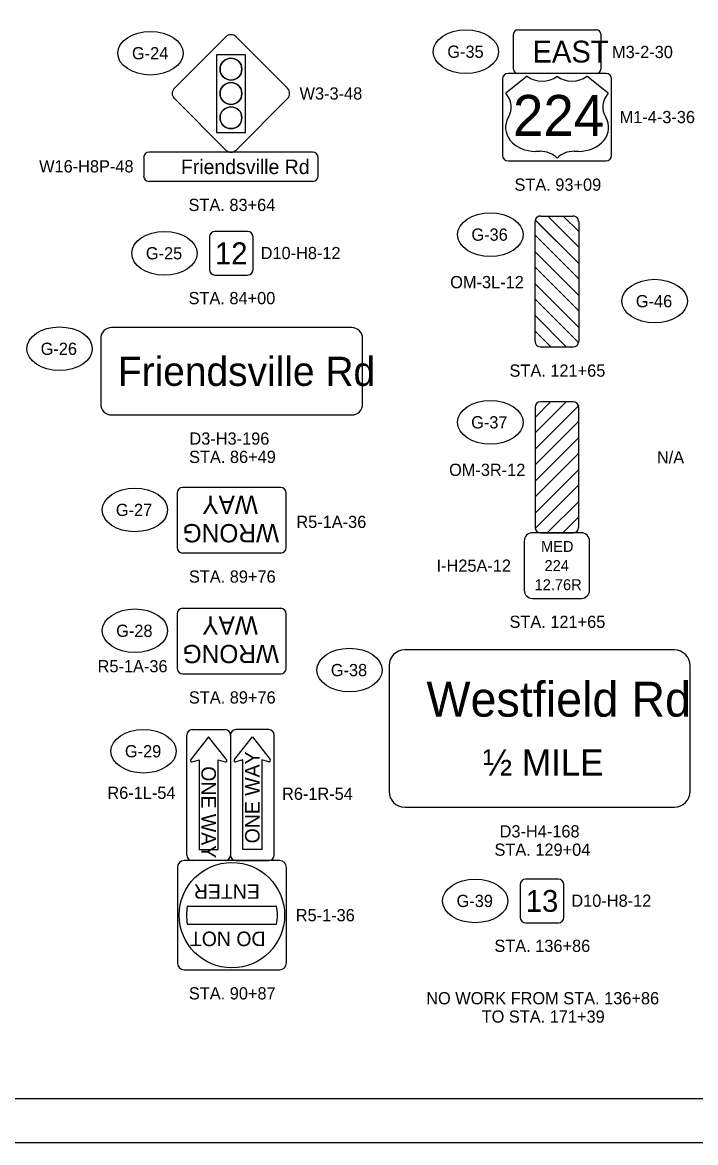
# Model space of a CAD drawing. Extents: x 0 to 34, y 0 to 22.
# Drawn here: x 9.39 to 17.1, y 0 to 12.83 of the extents above; entities that cross this region are included whole.
import ezdxf

# ---------------------------------------------------------------- set-up
doc = ezdxf.new("R2010")
doc.units = 0
for name, color, linetype in [('SH_Border', 7, 'Continuous'), ('SH_Cut_Line', 7, 'Continuous'), ('SH_Text', 7, 'Continuous'), ('SN_P_Signs', 7, 'Continuous')]:
    doc.layers.add(name, color=color, linetype=linetype)

msp = doc.modelspace()

# ---------------------------------------------------------------- linework, layer by layer
at = {"layer": 'SH_Border'}
msp.add_lwpolyline([(1.5, 21.5), (33.5, 21.5), (33.5, 0.5), (1.5, 0.5)], close=True, dxfattribs=at)
at = {"layer": 'SH_Cut_Line'}
msp.add_lwpolyline([(0, 0), (34, 0), (34, 22), (0, 22)], close=True, dxfattribs=at)
at = {"layer": 'SH_Text'}
for centre in [(10.855, 12.473), (14.468, 12.49), (14.748, 10.396), (11.015, 10.182), (16.631, 9.634), (9.813, 9.089), (14.748, 8.247), (10.676, 7.244), (10.676, 5.86), (13.135, 5.41), (10.775, 4.481), (14.575, 2.767)]:
    msp.add_ellipse(centre, major_axis=(0.375, 0), ratio=0.666667, dxfattribs=at)
at = {"layer": 'SN_P_Signs'}
for p, q in [((15.063, 12.741), (15.963, 12.741)), ((15.013, 12.291), (15.013, 12.691)), ((16.013, 12.691), (16.013, 12.291)), ((15.171, 12.209), (14.927, 12.014)), ((15.963, 12.241), (15.063, 12.241)), ((16.099, 12.014), (15.855, 12.209)), ((15.269, 11.35), (15.318, 11.35)), ((15.709, 11.35), (15.757, 11.35)), ((15.761, 10.065), (15.261, 10.565)), ((15.761, 10.254), (15.406, 10.609)), ((15.761, 10.431), (15.582, 10.609)), ((15.761, 9.888), (15.261, 10.388)), ((15.761, 9.7), (15.261, 10.2)), ((15.761, 9.523), (15.261, 10.023)), ((15.761, 9.334), (15.261, 9.834)), ((15.761, 9.158), (15.261, 9.658)), ((15.621, 9.109), (15.261, 9.469)), ((15.444, 9.109), (15.261, 9.292)), ((15.261, 8.126), (15.616, 8.481)), ((15.261, 8.303), (15.439, 8.481)), ((15.261, 7.938), (15.761, 8.438)), ((15.261, 7.761), (15.761, 8.261)), ((15.261, 7.572), (15.761, 8.072)), ((15.261, 7.395), (15.761, 7.895)), ((15.261, 7.207), (15.761, 7.707)), ((15.261, 7.03), (15.761, 7.53)), ((15.401, 6.981), (15.761, 7.341)), ((15.578, 6.981), (15.761, 7.164)), ((11.521, 4.646), (11.316, 4.386)), ((11.727, 4.386), (11.521, 4.646)), ((11.816, 4.386), (12.022, 4.646)), ((12.022, 4.646), (12.227, 4.386)), ((11.332, 4.361), (11.412, 4.381)), ((11.412, 4.381), (11.412, 3.354)), ((11.631, 3.354), (11.631, 4.381)), ((11.631, 4.381), (11.711, 4.361)), ((11.912, 4.381), (11.832, 4.361)), ((11.912, 3.354), (11.912, 4.381)), ((12.21, 4.361), (12.131, 4.381)), ((12.131, 4.381), (12.131, 3.354)), ((11.412, 3.354), (11.631, 3.354)), ((12.131, 3.354), (11.912, 3.354)), ((11.277, 2.708), (12.298, 2.708)), ((12.298, 2.499), (11.277, 2.499))]:
    msp.add_line(p, q, dxfattribs=at)
for points in [[(11.718, 12.66), (11.129, 12.071)], [(12.425, 12.071), (11.836, 12.66)], [(11.943, 11.567), (11.943, 12.456), (11.61, 12.456), (11.61, 11.567), (11.943, 11.567)], [(11.61, 11.567), (11.943, 11.567), (11.943, 12.456), (11.61, 12.456), (11.61, 11.567)], [(16.076, 12.241), (14.951, 12.241)], [(14.888, 12.178), (14.888, 11.303)], [(16.138, 11.303), (16.138, 12.178)], [(11.129, 11.953), (11.718, 11.364)], [(11.836, 11.364), (12.425, 11.953)], [(12.714, 11.339), (10.839, 11.339)], [(10.777, 11.277), (10.777, 11.068)], [(12.777, 11.068), (12.777, 11.277)], [(14.951, 11.241), (16.076, 11.241)], [(10.839, 11.006), (12.714, 11.006)], [(15.261, 9.172), (15.261, 10.547)], [(15.323, 10.609), (15.406, 10.609), (15.761, 10.254), (15.761, 10.065), (15.263, 10.563)], [(15.323, 10.609), (15.698, 10.609)], [(15.582, 10.609), (15.698, 10.609)], [(15.761, 10.547), (15.761, 10.431), (15.582, 10.609)], [(15.761, 10.547), (15.761, 9.172)], [(11.968, 10.432), (11.593, 10.432)], [(11.531, 10.37), (11.531, 9.995)], [(12.031, 9.995), (12.031, 10.37)], [(15.261, 10.2), (15.261, 10.388), (15.761, 9.888), (15.761, 9.7), (15.261, 10.2)], [(15.261, 9.834), (15.261, 10.023), (15.761, 9.523), (15.761, 9.334), (15.261, 9.834)], [(11.593, 9.932), (11.968, 9.932)], [(15.698, 9.109), (15.621, 9.109), (15.261, 9.469), (15.261, 9.658), (15.76, 9.159)], [(13.16, 9.331), (10.41, 9.331)], [(15.261, 9.172), (15.261, 9.292), (15.444, 9.109)], [(10.285, 9.206), (10.285, 8.456)], [(13.285, 8.456), (13.285, 9.206)], [(15.698, 9.109), (15.323, 9.109)], [(15.444, 9.109), (15.323, 9.109)], [(15.261, 8.419), (15.261, 8.303), (15.439, 8.481)], [(15.698, 8.481), (15.616, 8.481), (15.261, 8.126), (15.261, 7.938), (15.759, 8.435)], [(15.698, 8.481), (15.323, 8.481)], [(15.439, 8.481), (15.323, 8.481)], [(15.261, 8.419), (15.261, 7.044)], [(15.761, 7.044), (15.761, 8.419)], [(10.41, 8.331), (13.16, 8.331)], [(15.761, 8.072), (15.761, 8.261), (15.261, 7.761), (15.261, 7.572), (15.761, 8.072)], [(15.761, 7.707), (15.761, 7.895), (15.261, 7.395), (15.261, 7.207), (15.761, 7.707)], [(12.348, 7.501), (11.223, 7.501)], [(15.323, 6.981), (15.401, 6.981), (15.761, 7.341), (15.761, 7.53), (15.262, 7.031)], [(11.16, 7.438), (11.16, 6.813)], [(12.41, 6.813), (12.41, 7.438)], [(15.761, 7.044), (15.761, 7.164), (15.578, 6.981)], [(15.792, 6.981), (15.23, 6.981)], [(15.323, 6.981), (15.698, 6.981)], [(15.578, 6.981), (15.698, 6.981)], [(15.136, 6.888), (15.136, 6.325)], [(15.886, 6.325), (15.886, 6.888)], [(11.223, 6.751), (12.348, 6.751)], [(15.23, 6.231), (15.792, 6.231)], [(11.16, 6.055), (11.16, 5.43)], [(12.348, 6.117), (11.223, 6.117)], [(12.41, 5.43), (12.41, 6.055)], [(16.857, 5.64), (13.768, 5.64)], [(13.588, 5.46), (13.588, 4.02)], [(17.037, 4.02), (17.037, 5.46)], [(11.223, 5.367), (12.348, 5.367)], [(11.271, 3.291), (11.271, 4.666)], [(11.334, 4.729), (11.709, 4.729)], [(11.771, 4.666), (11.771, 3.291)], [(11.771, 4.666), (11.771, 3.291)], [(12.209, 4.729), (11.834, 4.729)], [(12.271, 3.291), (12.271, 4.666)], [(13.768, 3.84), (16.857, 3.84)], [(12.335, 3.229), (11.241, 3.229)], [(11.709, 3.229), (11.334, 3.229)], [(11.834, 3.229), (12.209, 3.229)], [(11.163, 3.151), (11.163, 2.057)], [(12.413, 2.057), (12.413, 3.151)], [(15.091, 2.954), (15.091, 2.579)], [(15.528, 3.017), (15.153, 3.017)], [(15.591, 2.579), (15.591, 2.954)], [(15.153, 2.517), (15.528, 2.517)], [(11.241, 1.979), (12.335, 1.979)]]:
    msp.add_lwpolyline(points, dxfattribs=at)
for centre, radius in [((11.777, 12.29), 0.125), ((11.777, 12.012), 0.125), ((11.777, 11.734), 0.125), ((11.788, 2.604), 0.604)]:
    msp.add_circle(centre, radius, dxfattribs=at)
for centre, radius, start, end in [((15.063, 12.691), 0.05, 90, 180), ((15.963, 12.691), 0.05, 0, 90), ((11.777, 12.601), 0.0833, 45, 135), ((11.777, 12.29), 0.125, 0, 180), ((11.777, 12.29), 0.125, 180, 0), ((14.951, 12.178), 0.0625, 90, 180), ((15.063, 12.291), 0.05, 180, 270), ((15.963, 12.291), 0.05, 270, 0), ((16.076, 12.178), 0.0625, 0, 90), ((11.187, 12.012), 0.0833, 135, 225), ((11.777, 12.012), 0.125, 0, 180), ((12.366, 12.012), 0.0833, 315, 45), ((11.777, 12.012), 0.125, 180, 0), ((11.777, 11.734), 0.125, 0, 180), ((11.777, 11.734), 0.125, 180, 0), ((10.839, 11.277), 0.0625, 90, 180), ((11.777, 11.423), 0.0833, 225, 315), ((12.714, 11.277), 0.0625, 0, 90), ((14.951, 11.303), 0.0625, 180, 270), ((16.076, 11.303), 0.0625, 270, 0), ((10.839, 11.068), 0.0625, 180, 270), ((12.714, 11.068), 0.0625, 270, 0), ((15.323, 10.547), 0.0625, 90, 180), ((15.323, 10.547), 0.0625, 90, 164.7237), ((15.698, 10.547), 0.0625, 0, 90), ((15.698, 10.547), 0.0625, 0, 90), ((11.593, 10.37), 0.0625, 90, 180), ((11.968, 10.37), 0.0625, 0, 90), ((11.593, 9.995), 0.0625, 180, 270), ((11.968, 9.995), 0.0625, 270, 0), ((10.41, 9.206), 0.125, 90, 180), ((13.16, 9.206), 0.125, 0, 90), ((15.323, 9.172), 0.0625, 180, 270), ((15.323, 9.172), 0.0625, 180, 270), ((15.698, 9.172), 0.0625, 270, 360), ((15.698, 9.172), 0.0625, 270, 348.268), ((15.323, 8.419), 0.0625, 90, 180), ((15.323, 8.419), 0.0625, 90, 180), ((15.698, 8.419), 0.0625, 0, 90), ((15.698, 8.419), 0.0625, 15.2763, 90), ((10.41, 8.456), 0.125, 180, 270), ((13.16, 8.456), 0.125, 270, 0), ((11.223, 7.438), 0.0625, 90, 180), ((12.348, 7.438), 0.0625, 0, 90), ((15.23, 6.888), 0.0938, 90, 180), ((15.323, 7.044), 0.0625, 180, 270), ((15.323, 7.044), 0.0625, 191.732, 270), ((15.698, 7.044), 0.0625, 270, 0), ((15.698, 7.044), 0.0625, 270, 0), ((15.792, 6.888), 0.0938, 0, 90), ((11.223, 6.813), 0.0625, 180, 270), ((12.348, 6.813), 0.0625, 270, 360), ((15.23, 6.325), 0.0938, 180, 270), ((15.792, 6.325), 0.0938, 270, 0), ((11.223, 6.055), 0.0625, 90, 180), ((12.348, 6.055), 0.0625, 0, 90), ((13.768, 5.46), 0.18, 90, 180), ((16.857, 5.46), 0.18, 0, 90), ((11.223, 5.43), 0.0625, 180, 270), ((12.348, 5.43), 0.0625, 270, 360), ((11.334, 4.666), 0.0625, 90, 180), ((11.709, 4.666), 0.0625, 360, 90), ((11.834, 4.666), 0.0625, 90, 180), ((12.209, 4.666), 0.0625, 360, 90), ((11.328, 4.376), 0.0157, 141.6275, 284.2432), ((11.715, 4.376), 0.0157, 255.7826, 38.342), ((11.828, 4.376), 0.0157, 141.658, 284.2174), ((12.214, 4.376), 0.0157, 255.7568, 38.3725), ((13.768, 4.02), 0.18, 180, 270), ((16.857, 4.02), 0.18, 270, 360), ((11.241, 3.151), 0.0781, 90, 180), ((11.334, 3.291), 0.0625, 180, 270), ((11.709, 3.291), 0.0625, 270, 360), ((11.834, 3.291), 0.0625, 180, 270), ((12.209, 3.291), 0.0625, 270, 360), ((12.335, 3.151), 0.0781, 0, 90), ((15.153, 2.954), 0.0625, 90, 180), ((15.528, 2.954), 0.0625, 0, 90), ((11.788, 2.604), 0.521, 168.463, 191.537), ((11.788, 2.604), 0.521, 348.463, 11.537), ((15.153, 2.579), 0.0625, 180, 270), ((15.528, 2.579), 0.0625, 270, 0), ((11.241, 2.057), 0.0781, 180, 270), ((12.335, 2.057), 0.0781, 270, 360)]:
    msp.add_arc(centre, radius, start, end, dxfattribs=at)
for centre, major_axis, start_param, end_param in [((15.342, 12.349), (-0.244, 0), 0.795399, 2.346194), ((15.684, 12.349), (-0.244, 0), 0.795399, 2.346194), ((14.647, 11.857), (0.342, 0), 5.838949, 6.894067), ((16.379, 11.857), (-0.342, 0), 5.672304, 6.727422), ((15.265, 11.623), (0.342, 0), 2.702327, 4.723529), ((15.761, 11.623), (-0.342, 0), 1.559657, 3.580859), ((15.318, 11.155), (-0.244, 0), 3.785094, 4.712389), ((15.709, 11.155), (-0.244, 0), 4.712389, 5.639684)]:
    msp.add_ellipse(centre, major_axis=major_axis, ratio=0.8, start_param=start_param, end_param=end_param, dxfattribs=at)

# ---------------------------------------------------------------- texts
at = {"layer": 'SH_Text'}
for s, p in [('G-24', (10.643, 12.403)), ('G-35', (14.256, 12.42)), ('M3-2-30', (16.143, 12.417)), ('W3-3-48', (12.563, 11.942)), ('M1-4-3-36', (16.23, 11.672)), ('W16-H8P-48', (9.579, 11.108)), ('STA. 93+09', (15.025, 10.898)), ('STA. 83+64', (11.291, 10.666)), ('G-36', (14.532, 10.326)), ('G-25', (10.802, 10.112)), ('D10-H8-12', (12.117, 10.115)), ('OM-3L-12', (14.289, 9.782)), ('STA. 84+00', (11.291, 9.599)), ('G-46', (16.416, 9.564)), ('G-26', (9.597, 9.019)), ('STA. 121+65', (14.968, 8.769)), ('G-37', (14.529, 8.177)), ('D3-H3-196', (11.301, 7.991)), ('STA. 86+49', (11.297, 7.781)), ('N/A', (16.657, 7.776)), ('OM-3R-12', (14.276, 7.633)), ('G-27', (10.458, 7.174)), ('R5-1A-36', (12.526, 7.037)), ('I-H25A-12', (14.132, 6.536)), ('STA. 89+76', (11.295, 6.411)), ('STA. 121+65', (14.968, 5.893)), ('G-28', (10.462, 5.79)), ('R5-1A-36', (10.249, 5.385)), ('G-38', (12.921, 5.34)), ('STA. 89+76', (11.295, 5.027)), ('G-29', (10.562, 4.411)), ('R6-1L-54', (10.361, 3.935)), ('R6-1R-54', (12.362, 3.924)), ('D3-H4-168', (14.855, 3.494)), ('STA. 129+04', (14.796, 3.284)), ('G-39', (14.362, 2.697)), ('D10-H8-12', (15.677, 2.7)), ('R5-1-36', (12.519, 2.534)), ('STA. 136+86', (14.795, 2.183)), ('STA. 90+87', (11.295, 1.639)), ('NO WORK FROM STA. 136+86', (14.014, 1.583)), ('TO STA. 171+39', (14.649, 1.373))]:
    msp.add_text(s, height=0.14, dxfattribs=at).set_placement(p)
at = {"layer": 'SN_P_Signs'}
for s, height, p in [('EAST', 0.25, (15.231, 12.366)), ('224', 0.4688, (15.008, 11.526)), ('Friendsville Rd', 0.16665, (11.204, 11.089)), ('12', 0.25, (11.594, 10.057)), ('Friendsville Rd', 0.33333, (10.481, 8.664)), ('MED', 0.125, (15.33, 6.763)), ('224', 0.125, (15.37, 6.544)), ('12.76R', 0.125, (15.256, 6.325)), ('Westfield Rd', 0.39984, (14.017, 4.877)), ('½ MILE', 0.3, (14.664, 4.202)), ('13', 0.25, (15.155, 2.642))]:
    msp.add_text(s, height=height, dxfattribs=at).set_placement(p)
for s, height, rotation, p in [('WAY', 0.2094, 180, (12.086, 7.407)), ('WRONG', 0.2094, 180, (12.328, 7.082)), ('WAY', 0.2094, 180, (12.086, 6.024)), ('WRONG', 0.2094, 180, (12.328, 5.699)), ('ONE WAY', 0.1667, 90, (12.105, 3.426)), ('ONE WAY', 0.1667, 270, (11.438, 4.309)), ('ENTER', 0.1667, 180, (12.107, 2.958)), ('DO NOT', 0.1667, 180, (12.173, 2.416))]:
    msp.add_text(s, height=height, rotation=rotation, dxfattribs=at).set_placement(p)

doc.saveas('drawing.dxf')
